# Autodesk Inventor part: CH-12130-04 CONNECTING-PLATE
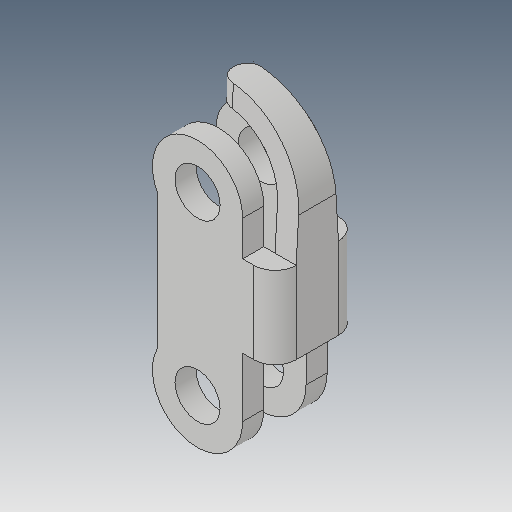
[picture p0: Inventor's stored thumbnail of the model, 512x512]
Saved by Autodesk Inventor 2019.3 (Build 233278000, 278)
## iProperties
Created: 2012-09
Part Number: CH-12130-04 CONNECTING-PLATE
Material: Ogólny
Document SubType Name: Modeling
Designer: CADENGINEERING4
Density: 1 g/cm^3
Appearance: Domyślna
Author: CADENGINEERING4
Revision Number: ÈÎºÎ
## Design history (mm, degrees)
feature "Ô²½Ç2"
feature "ÇÐ³ý-À­Éì3"
node "Bryła1"
node "Bryła2"
